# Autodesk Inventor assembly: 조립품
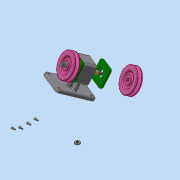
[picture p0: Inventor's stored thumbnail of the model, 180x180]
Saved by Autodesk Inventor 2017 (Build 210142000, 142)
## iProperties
Part Number: 조립품
Material: 일반
Document SubType Name: Assembly
Designer: mrc
Author: mrc
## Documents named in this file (10)
- C:\Users\mrc\Desktop\701106V1023\조립품.iam
- C:\Users\mrc\Desktop\701106V1023\V-벨트풀리.ipt
- C:\Users\mrc\Desktop\701106V1023\너트 M10x1.ipt
- C:\Users\mrc\Desktop\701106V1023\베어링 6004.ipt
- C:\Users\mrc\Desktop\701106V1023\본체.ipt
- C:\Users\mrc\Desktop\701106V1023\볼트 M4.ipt
- C:\Users\mrc\Desktop\701106V1023\오일 실 17 30 5.ipt
- C:\Users\mrc\Desktop\701106V1023\축.ipt
- C:\Users\mrc\Desktop\701106V1023\커버.ipt
- C:\Users\mrc\Desktop\701106V1023\키 5 x 5 x 12.ipt
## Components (2 placed, 1 different names)
1. V-벨트풀리:1
2. V-벨트풀리:2
